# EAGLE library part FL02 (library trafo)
TRANSFORMER 2 primary winding, 2 secondary windings, mounting holes BLOCK
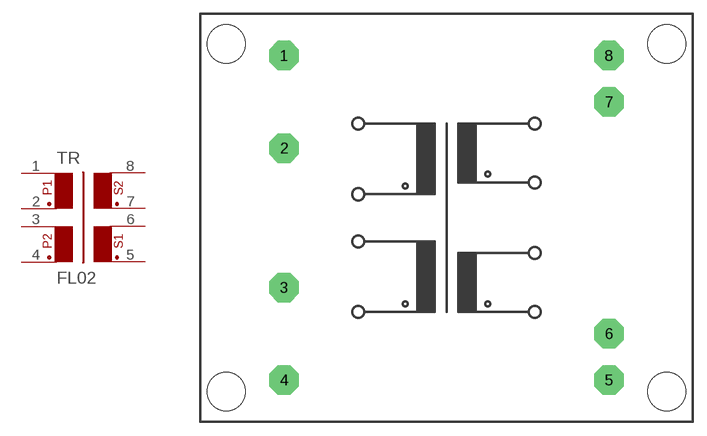
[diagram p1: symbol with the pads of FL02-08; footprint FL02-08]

Designator prefix TR

## FL02  [FL02-08]
1  1  pas
2  2  pas
3  3  pas
4  4  pas
5  5  pas
6  6  pas
7  7  pas
8  8  pas

## Footprint FL02-08 (pad centres in mm)
TRANSFORMER 2 primary winding, 2 secondary windings, mounting holes
drill 1.194 pad 3.175 octagon: 1 -17.501,17.501; 2 -17.501,7.518; 3 -17.501,-7.518; 4 -17.501,-17.501; 5 17.501,-17.501; 6 17.501,-12.497; 7 17.501,12.497; 8 17.501,17.501
hole 4.115 at 23.749,18.745
hole 4.115 at 23.749,-18.745
hole 4.115 at -23.749,-18.745
hole 4.115 at -23.749,18.745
